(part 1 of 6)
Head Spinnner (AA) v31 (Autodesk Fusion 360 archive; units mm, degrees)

design "Head Spinnner (AA)" references "DC Motor Controller", "6V AA Battery Holder", "9V Battery & T Connector", "Plastic Latching Push Button", "LED + Cap", "Kwali on Pillar", "3 State Switch", "DC 6V 5RPM 2-Wire Motor"
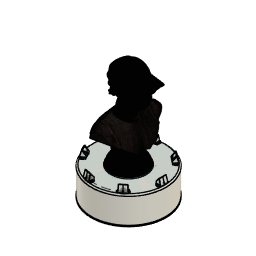
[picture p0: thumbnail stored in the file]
parameter "bustDiameter" = 83.82
parameter "wallThickness" = 3.175
parameter "clearance" = 0.254
parameter "buttonOffset" = 6.35
sketch "Profile" plane through (0, 0, 0) normal (0, 0, 1) x axis (1, 0, 0)
  circle C1 centre (0, 0) radius 41.91
  circle C2 centre (0, 0) radius 88.9
  point P1 (0, 0)
  point P2 (0, 0)
  coincident P1 P2
  concentric C1 C2
  dimension "d1" diameter C1 = 83.82 (= "bustDiameter")
  dimension "d2" diameter C2 = 177.8
extrude "Extrude1" new body sketch "Profile" along normal blind 63.5
shell "Shell1" innerThickness 3.175 (= "wallThickness")
fillet "Fillet1" radius 3.175
extrude "Extrude2" sketch "Profile" profile of C1 blind -132.08
sketch "PoR Clearance for Shell" plane through (0, 0, 63.5) normal (0, 0, 1) x axis (-1, 0, 0)
  circle C1 centre (0, 0) radius 41.91
  circle C2 centre (0, 0) radius 85.725
  circle C3 centre (0, 0) radius 42.164
  dimension "d136" = 0.254 (= "clearance")
extrude "Extrude4" cut sketch "PoR Clearance for Shell" profile of C1 C3 against normal blind 88.9
extrude "Extrude3" new body sketch "Profile" profile of C1 along normal blind 3.175
extrude "Extrude1" new body sketch "Profile" profile of C1 against normal blind 3.175
component_from_bodies "Body->Comp1"
component_from_bodies "Body->Comp2"
joint "Assemble1" alignAngle 0 alignOffsetX 0 alignOffsetY 0 alignOffsetZ 0
joint "Assemble2" alignAngle 0 alignOffsetX 0 alignOffsetY 0 alignOffsetZ 0
component_insert "Component Insert1"
component_insert "Component Insert2"
sketch "Gear OD" plane through (0, 0, 57.15) normal (0, 0, -1) x axis (0.9809, 0.1944, 0)
  circle C1 centre (0, 0) radius 41.91
  circle C2 centre (0, 0) radius 15.875
  concentric C1 C2
  dimension "d24" diameter C2 = 31.75
sketch "Sketch1" plane through (0, 0, 0) normal (0, 0, 1) x axis (1, 0, 0)
  circle C1 centre (0, 0) radius 12.6492
  circle C2 centre (0, 0) radius 3.175
extrude "Extrude1" new body sketch "Sketch1" along normal blind 25.4
sketch "Sketch2" plane through (0, 0, 0) normal (0, 0, 1) x axis (1, 0, 0)
  curve K1 (15.867, -0.5013) -> (13.5023, -1.2654)
  curve K2 (15.867, 0.5013) -> (13.5023, 1.2654)
  line L1 (13.5023, -1.2654) -> (12.584, -1.1803)
  line L2 (13.5023, 1.2654) -> (12.584, 1.1803)
  line L3 (12.584, 1.1803) -> (12.584, -1.1803)
  arc A1 centre (0, 0) radius 15.8749 clockwise from (15.867, 0.5013) to (15.867, -0.5013)
  dimension "d464" angle = 103.278
extrude "Extrude2" add sketch "Sketch2" along normal blind 25.4
fillet "Fillet1" radius 0.8382
circular_pattern "C-Pattern1" countU 20 TotalAngle 360
sketch "Sketch3" plane through (0, 0, 0) normal (0, 0, 1) x axis (1, 0, 0)
  circle C1 centre (0, 0) radius 14.4318
position "Position1"
combine "Combine1"
sketch "Holes for Shell Btm" plane through (0, 0, 0) normal (0, 0, -1) x axis (1, 0, 0)
  line L1 (0, -88.9) -> (0, -79.375)
  line L2 (0, -88.9) -> (0, 0)
  circle C1 centre (0, 0) radius 85.725
  circle C2 centre (0, 0) radius 88.9
  circle C3 centre (0, 0) radius 79.375
  circle C4 centre (0, -84.1375) radius 1.45
  circle C5 centre (65.7813, -52.4589) radius 1.45
  circle C6 centre (82.028, 18.7224) radius 1.45
  circle C7 centre (36.5059, 75.8053) radius 1.45
  circle C8 centre (-36.5059, 75.8053) radius 1.45
  circle C9 centre (-82.028, 18.7224) radius 1.45
  circle C10 centre (-65.7813, -52.4589) radius 1.45
  point P4 (0, -79.375)
  point P8 (0, -88.9)
  point P5 (0, -84.1375)
  point P6 (0, -84.1375)
  point P3 (0, 0)
  point P7 (0, 0)
  concentric C1 C3
  coincident C3 P4
  coincident C2 P8
  vertical L1
  midpoint L1 P5
  coincident P5 P6
  coincident P3 P7
  coincident C2 P8
  vertical L2
  dimension "d33" distance C2 C3 = 9.525 (= "( 3 / 8 ) * 1 in")
  dimension "d34" diameter C4 = 2.9
  dimension "d44" C-Pattern1-Angle = 360
extrude "Extrude1" add sketch "Holes for Shell Btm" profile of C1 C2 C3 C4 no distance stored
chamfer "Chamfer1" distance 6.35
sketch "Bottom Profile" plane through (0, 0, 0) normal (0, 0, -1) x axis (1, 0, 0)
  circle C1 centre (0, 0) radius 79.375
  circle C2 centre (0, 0) radius 88.9
  circle C3 centre (0, 0) radius 88.9
  concentric C1 C3
extrude "Extrude1" new body sketch "Bottom Profile" along normal blind 2.54
extrude "Extrude2" cut sketch "Holes for Shell Btm" profile of C4 C5 C6 C7 C8 C9 C10 distance 12.7
sketch "Bottom Holes" plane through (0, 0, -2.54) normal (0, 0, -1) x axis (1, 0, 0)
  circle C1 centre (36.5059, 75.8053) radius 1.45
  circle C2 centre (-65.7813, -52.4589) radius 1.45
  circle C3 centre (82.028, 18.7224) radius 1.45
  circle C4 centre (-36.5059, 75.8053) radius 1.45
  circle C5 centre (0, -84.1375) radius 1.45
  circle C6 centre (65.7813, -52.4589) radius 1.45
  circle C7 centre (-82.028, 18.7224) radius 1.45
  circle C8 centre (0, 0) radius 88.9
  circle C9 centre (0, -84.1375) radius 1.804
  circle C10 centre (65.7813, -52.4589) radius 1.804
  circle C11 centre (82.028, 18.7224) radius 1.804
  circle C12 centre (36.5059, 75.8053) radius 1.804
  circle C13 centre (-36.5059, 75.8053) radius 1.804
  circle C14 centre (-82.028, 18.7224) radius 1.804
  circle C15 centre (-65.7813, -52.4589) radius 1.804
  dimension "d526" = 0.354 (= "0.01 in + 0.1 mm")
  dimension "d52" C-Pattern1-Angle = 360
extrude "Extrude3" cut sketch "Bottom Holes" profile of C1 C2 C3 C4 C5 C6 C7 C9 C10 C11 C12 C13 C14 C15 against normal blind 38.1
chamfer "Chamfer1" distance 1.524
sketch "Sketch1" plane through (0, 0, 0) normal (0, 0, 1) x axis (1, 0, 0)
  circle C1 centre (0, 0) radius 19.865
  circle C2 centre (0, 0) radius 3.175
extrude "Extrude1" new body sketch "Sketch1" along normal blind 6.35
sketch "Sketch2" plane through (0, 0, 0) normal (0, 0, 1) x axis (1, 0, 0)
  curve K1 (23.0847, -0.5321) -> (20.2961, -1.3673)
  curve K2 (23.0847, 0.5321) -> (20.2961, 1.3673)
  line L1 (20.2961, -1.3673) -> (19.8101, -1.3352)
  line L2 (20.2961, 1.3673) -> (19.8101, 1.3352)
  line L3 (19.8101, 1.3352) -> (19.8101, -1.3352)
  arc A1 centre (0, 0) radius 23.0908 clockwise from (23.0847, 0.5321) to (23.0847, -0.5321)
extrude "Extrude2" add sketch "Sketch2" along normal blind 6.35
fillet "Fillet1" radius 0.8382
circular_pattern "C-Pattern1" countU 30 TotalAngle 360
sketch "Sketch3" plane through (0, 0, 0) normal (0, 0, 1) x axis (1, 0, 0)
  circle C1 centre (0, 0) radius 21.6477
sketch "Center Gear Pitch Diameter" plane through (0, 0, 0) normal (0, 0, -1) x axis (1, 0, 0)
  curve K1 (19.9155, 5.6104) -> (19.4097, 7.1671)
  curve K2 (21.3053, 8.9033) -> (19.4097, 7.1671)
  curve K3 (20.8725, 9.8754) -> (18.3138, 9.6284)
  curve K4 (18.3138, 9.6284) -> (17.4954, 11.046)
  curve K5 (18.9887, 13.1384) -> (17.4954, 11.046)
  curve K6 (18.3632, 13.9993) -> (15.9118, 13.2257)
  curve K7 (15.9118, 13.2257) -> (14.8165, 14.4421)
  curve K8 (15.8421, 16.7993) -> (14.8165, 14.4421)
  curve K9 (15.0513, 17.5113) -> (12.8143, 16.2449)
  curve K10 (12.8143, 16.2449) -> (11.49, 17.2071)
  curve K11 (12.0031, 19.7259) -> (11.49, 17.2071)
  curve K12 (11.0816, 20.258) -> (9.1567, 18.5542)
  curve K13 (9.1567, 18.5542) -> (7.6614, 19.22)
  curve K14 (7.6396, 21.7904) -> (7.6614, 19.22)
  curve K15 (6.6276, 22.1193) -> (5.099, 20.0525)
  curve K16 (5.099, 20.0525) -> (3.4979, 20.3928)
  curve K17 (2.9421, 22.9026) -> (3.4979, 20.3928)
  curve K18 (1.8839, 23.0139) -> (0.8184, 20.6745)
  curve K19 (0.8184, 20.6745) -> (-0.8184, 20.6745)
  curve K20 (-1.8839, 23.0139) -> (-0.8184, 20.6745)
  curve K21 (-2.9421, 22.9026) -> (-3.4979, 20.3928)
  curve K22 (-3.4979, 20.3928) -> (-5.099, 20.0525)
  curve K23 (-6.6276, 22.1193) -> (-5.099, 20.0525)
  curve K24 (-7.6396, 21.7904) -> (-7.6614, 19.22)
  curve K25 (-7.6614, 19.22) -> (-9.1567, 18.5542)
  curve K26 (-11.0816, 20.258) -> (-9.1567, 18.5542)
  curve K27 (-12.0031, 19.7259) -> (-11.49, 17.2071)
  curve K28 (-11.49, 17.2071) -> (-12.8143, 16.2449)
  curve K29 (-15.0513, 17.5113) -> (-12.8143, 16.2449)
  curve K30 (-15.8421, 16.7993) -> (-14.8165, 14.4421)
  curve K31 (-14.8165, 14.4421) -> (-15.9118, 13.2257)
  curve K32 (-18.3632, 13.9993) -> (-15.9118, 13.2257)
  curve K33 (-18.9887, 13.1384) -> (-17.4954, 11.046)
  curve K34 (-17.4954, 11.046) -> (-18.3138, 9.6284)
  curve K35 (-20.8725, 9.8754) -> (-18.3138, 9.6284)
  curve K36 (-21.3053, 8.9033) -> (-19.4097, 7.1671)
  curve K37 (-19.4097, 7.1671) -> (-19.9155, 5.6104)
  curve K38 (-22.4696, 5.32) -> (-19.9155, 5.6104)
  curve K39 (-22.6909, 4.2792) -> (-20.4757, 2.975)
  curve K40 (-20.4757, 2.975) -> (-20.6468, 1.3471)
  curve K41 (-23.0847, 0.5321) -> (-20.6468, 1.3471)
  curve K42 (-23.0847, -0.5321) -> (-20.6468, -1.3471)
  curve K43 (-20.6468, -1.3471) -> (-20.4757, -2.975)
  curve K44 (-22.6909, -4.2792) -> (-20.4757, -2.975)
  curve K45 (-22.4696, -5.32) -> (-19.9155, -5.6104)
  curve K46 (-19.9155, -5.6104) -> (-19.4097, -7.1671)
  curve K47 (-21.3053, -8.9033) -> (-19.4097, -7.1671)
  curve K48 (-20.8725, -9.8754) -> (-18.3138, -9.6284)
  curve K49 (-18.3138, -9.6284) -> (-17.4954, -11.046)
  curve K50 (-18.9887, -13.1384) -> (-17.4954, -11.046)
  curve K51 (-18.3632, -13.9993) -> (-15.9118, -13.2257)
  curve K52 (-15.9118, -13.2257) -> (-14.8165, -14.4421)
  curve K53 (-15.8421, -16.7993) -> (-14.8165, -14.4421)
  curve K54 (-15.0513, -17.5113) -> (-12.8143, -16.2449)
  curve K55 (-12.8143, -16.2449) -> (-11.49, -17.2071)
  curve K56 (-12.0031, -19.7259) -> (-11.49, -17.2071)
  curve K57 (-11.0816, -20.258) -> (-9.1567, -18.5542)
  curve K58 (-9.1567, -18.5542) -> (-7.6614, -19.22)
  curve K59 (-7.6396, -21.7904) -> (-7.6614, -19.22)
  curve K60 (-6.6276, -22.1193) -> (-5.099, -20.0525)
  curve K61 (-5.099, -20.0525) -> (-3.4979, -20.3928)
  curve K62 (-2.9421, -22.9026) -> (-3.4979, -20.3928)
  curve K63 (-1.8839, -23.0139) -> (-0.8184, -20.6745)
  curve K64 (-0.8184, -20.6745) -> (0.8184, -20.6745)
  curve K65 (1.8839, -23.0139) -> (0.8184, -20.6745)
  curve K66 (2.9421, -22.9026) -> (3.4979, -20.3928)
  curve K67 (3.4979, -20.3928) -> (5.099, -20.0525)
  curve K68 (6.6276, -22.1193) -> (5.099, -20.0525)
  curve K69 (7.6396, -21.7904) -> (7.6614, -19.22)
  curve K70 (7.6614, -19.22) -> (9.1567, -18.5542)
  curve K71 (11.0816, -20.258) -> (9.1567, -18.5542)
  curve K72 (12.0031, -19.7259) -> (11.49, -17.2071)
  curve K73 (11.49, -17.2071) -> (12.8143, -16.2449)
  curve K74 (15.0513, -17.5113) -> (12.8143, -16.2449)
  curve K75 (15.8421, -16.7993) -> (14.8165, -14.4421)
  curve K76 (14.8165, -14.4421) -> (15.9118, -13.2257)
  curve K77 (18.3632, -13.9993) -> (15.9118, -13.2257)
  curve K78 (18.9887, -13.1384) -> (17.4954, -11.046)
  curve K79 (17.4954, -11.046) -> (18.3138, -9.6284)
  curve K80 (20.8725, -9.8754) -> (18.3138, -9.6284)
  curve K81 (21.3053, -8.9033) -> (19.4097, -7.1671)
  curve K82 (19.4097, -7.1671) -> (19.9155, -5.6104)
  curve K83 (22.4696, -5.32) -> (19.9155, -5.6104)
  curve K84 (22.6909, -4.2792) -> (20.4757, -2.975)
  curve K85 (20.4757, -2.975) -> (20.6468, -1.3471)
  curve K86 (23.0847, -0.5321) -> (20.6468, -1.3471)
  curve K87 (23.0847, 0.5321) -> (20.6468, 1.3471)
  curve K88 (20.6468, 1.3471) -> (20.4757, 2.975)
  curve K89 (22.6909, 4.2792) -> (20.4757, 2.975)
  curve K90 (22.4696, 5.32) -> (19.9155, 5.6104)
  arc A1 centre (0, 0) radius 23.0908 clockwise from (20.8725, 9.8754) to (21.3053, 8.9033)
  arc A2 centre (0, 0) radius 23.0908 clockwise from (18.3632, 13.9993) to (18.9887, 13.1384)
  arc A3 centre (0, 0) radius 23.0908 clockwise from (15.0513, 17.5113) to (15.8421, 16.7993)
  arc A4 centre (0, 0) radius 23.0908 clockwise from (11.0816, 20.258) to (12.0031, 19.7259)
  arc A5 centre (0, 0) radius 23.0908 clockwise from (6.6276, 22.1193) to (7.6396, 21.7904)
  arc A6 centre (0, 0) radius 23.0908 clockwise from (1.8839, 23.0139) to (2.9421, 22.9026)
  arc A7 centre (0, 0) radius 23.0908 clockwise from (-2.9421, 22.9026) to (-1.8839, 23.0139)
  arc A8 centre (0, 0) radius 23.0908 clockwise from (-7.6396, 21.7904) to (-6.6276, 22.1193)
  arc A9 centre (0, 0) radius 23.0908 clockwise from (-12.0031, 19.7259) to (-11.0816, 20.258)
  arc A10 centre (0, 0) radius 23.0908 clockwise from (-15.8421, 16.7993) to (-15.0513, 17.5113)
  arc A11 centre (0, 0) radius 23.0908 clockwise from (-18.9887, 13.1384) to (-18.3632, 13.9993)
  arc A12 centre (0, 0) radius 23.0908 clockwise from (-21.3053, 8.9033) to (-20.8725, 9.8754)
  arc A13 centre (0, 0) radius 23.0908 clockwise from (-22.6909, 4.2792) to (-22.4696, 5.32)
  arc A14 centre (0, 0) radius 23.0908 clockwise from (-23.0847, -0.5321) to (-23.0847, 0.5321)
  arc A15 centre (0, 0) radius 23.0908 clockwise from (-22.4696, -5.32) to (-22.6909, -4.2792)
  arc A16 centre (0, 0) radius 23.0908 clockwise from (-20.8725, -9.8754) to (-21.3053, -8.9033)
  arc A17 centre (0, 0) radius 23.0908 clockwise from (-18.3632, -13.9993) to (-18.9887, -13.1384)
  arc A18 centre (0, 0) radius 23.0908 clockwise from (-15.0513, -17.5113) to (-15.8421, -16.7993)
  arc A19 centre (0, 0) radius 23.0908 clockwise from (-11.0816, -20.258) to (-12.0031, -19.7259)
  arc A20 centre (0, 0) radius 23.0908 clockwise from (-6.6276, -22.1193) to (-7.6396, -21.7904)
  arc A21 centre (0, 0) radius 23.0908 clockwise from (-1.8839, -23.0139) to (-2.9421, -22.9026)
  arc A22 centre (0, 0) radius 23.0908 clockwise from (2.9421, -22.9026) to (1.8839, -23.0139)
  arc A23 centre (0, 0) radius 23.0908 clockwise from (7.6396, -21.7904) to (6.6276, -22.1193)
  arc A24 centre (0, 0) radius 23.0908 clockwise from (12.0031, -19.7259) to (11.0816, -20.258)
  arc A25 centre (0, 0) radius 23.0908 clockwise from (15.8421, -16.7993) to (15.0513, -17.5113)
  arc A26 centre (0, 0) radius 23.0908 clockwise from (18.9887, -13.1384) to (18.3632, -13.9993)
  arc A27 centre (0, 0) radius 23.0908 clockwise from (21.3053, -8.9033) to (20.8725, -9.8754)
  arc A28 centre (0, 0) radius 23.0908 clockwise from (22.6909, -4.2792) to (22.4696, -5.32)
  arc A29 centre (0, 0) radius 23.0908 clockwise from (23.0847, 0.5321) to (23.0847, -0.5321)
  arc A30 centre (0, 0) radius 23.0908 clockwise from (22.4696, 5.32) to (22.6909, 4.2792)
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extrude "Extrude5" add sketch "Center Gear Pitch Diameter" against normal blind 6.35
sketch "Motor Shaft Profile for Gear" plane through (0, 0, 0) normal (0, 0, -1) x axis (1, 0, 0)
  curve K1 (19.9155, 5.6104) -> (19.4097, 7.1671)
  curve K2 (21.3053, 8.9033) -> (19.4097, 7.1671)
  curve K3 (20.8725, 9.8754) -> (18.3138, 9.6284)
  curve K4 (18.3138, 9.6284) -> (17.4954, 11.046)
  curve K5 (18.9887, 13.1384) -> (17.4954, 11.046)
  curve K6 (18.3632, 13.9993) -> (15.9118, 13.2257)
  curve K7 (15.9118, 13.2257) -> (14.8165, 14.4421)
  curve K8 (15.8421, 16.7993) -> (14.8165, 14.4421)
  curve K9 (15.0513, 17.5113) -> (12.8143, 16.2449)
  curve K10 (12.8143, 16.2449) -> (11.49, 17.2071)
  curve K11 (12.0031, 19.7259) -> (11.49, 17.2071)
  curve K12 (11.0816, 20.258) -> (9.1567, 18.5542)
  curve K13 (9.1567, 18.5542) -> (7.6614, 19.22)
  curve K14 (7.6396, 21.7904) -> (7.6614, 19.22)
  curve K15 (6.6276, 22.1193) -> (5.099, 20.0525)
  curve K16 (5.099, 20.0525) -> (3.4979, 20.3928)
  curve K17 (2.9421, 22.9026) -> (3.4979, 20.3928)
  curve K18 (1.8839, 23.0139) -> (0.8184, 20.6745)
  curve K19 (0.8184, 20.6745) -> (-0.8184, 20.6745)
  curve K20 (-1.8839, 23.0139) -> (-0.8184, 20.6745)
  curve K21 (-2.9421, 22.9026) -> (-3.4979, 20.3928)
  curve K22 (-3.4979, 20.3928) -> (-5.099, 20.0525)
  curve K23 (-6.6276, 22.1193) -> (-5.099, 20.0525)
  curve K24 (-7.6396, 21.7904) -> (-7.6614, 19.22)
  curve K25 (-7.6614, 19.22) -> (-9.1567, 18.5542)
  curve K26 (-11.0816, 20.258) -> (-9.1567, 18.5542)
  curve K27 (-12.0031, 19.7259) -> (-11.49, 17.2071)
  curve K28 (-11.49, 17.2071) -> (-12.8143, 16.2449)
  curve K29 (-15.0513, 17.5113) -> (-12.8143, 16.2449)
  curve K30 (-15.8421, 16.7993) -> (-14.8165, 14.4421)
  curve K31 (-14.8165, 14.4421) -> (-15.9118, 13.2257)
  curve K32 (-18.3632, 13.9993) -> (-15.9118, 13.2257)
  curve K33 (-18.9887, 13.1384) -> (-17.4954, 11.046)
  curve K34 (-17.4954, 11.046) -> (-18.3138, 9.6284)
  curve K35 (-20.8725, 9.8754) -> (-18.3138, 9.6284)
  curve K36 (-21.3053, 8.9033) -> (-19.4097, 7.1671)
  curve K37 (-19.4097, 7.1671) -> (-19.9155, 5.6104)
  curve K38 (-22.4696, 5.32) -> (-19.9155, 5.6104)
  curve K39 (-22.6909, 4.2792) -> (-20.4757, 2.975)
  curve K40 (-20.4757, 2.975) -> (-20.6468, 1.3471)
  curve K41 (-23.0847, 0.5321) -> (-20.6468, 1.3471)
  curve K42 (-23.0847, -0.5321) -> (-20.6468, -1.3471)
  curve K43 (-20.6468, -1.3471) -> (-20.4757, -2.975)
  curve K44 (-22.6909, -4.2792) -> (-20.4757, -2.975)
  curve K45 (-22.4696, -5.32) -> (-19.9155, -5.6104)
  curve K46 (-19.9155, -5.6104) -> (-19.4097, -7.1671)
  curve K47 (-21.3053, -8.9033) -> (-19.4097, -7.1671)
  curve K48 (-20.8725, -9.8754) -> (-18.3138, -9.6284)
  curve K49 (-18.3138, -9.6284) -> (-17.4954, -11.046)
  curve K50 (-18.9887, -13.1384) -> (-17.4954, -11.046)
  curve K51 (-18.3632, -13.9993) -> (-15.9118, -13.2257)
  curve K52 (-15.9118, -13.2257) -> (-14.8165, -14.4421)
  curve K53 (-15.8421, -16.7993) -> (-14.8165, -14.4421)
  curve K54 (-15.0513, -17.5113) -> (-12.8143, -16.2449)
  curve K55 (-12.8143, -16.2449) -> (-11.49, -17.2071)
  curve K56 (-12.0031, -19.7259) -> (-11.49, -17.2071)
  curve K57 (-11.0816, -20.258) -> (-9.1567, -18.5542)
  curve K58 (-9.1567, -18.5542) -> (-7.6614, -19.22)
  curve K59 (-7.6396, -21.7904) -> (-7.6614, -19.22)
  curve K60 (-6.6276, -22.1193) -> (-5.099, -20.0525)
  curve K61 (-5.099, -20.0525) -> (-3.4979, -20.3928)
  curve K62 (-2.9421, -22.9026) -> (-3.4979, -20.3928)
  curve K63 (-1.8839, -23.0139) -> (-0.8184, -20.6745)
  curve K64 (-0.8184, -20.6745) -> (0.8184, -20.6745)
  curve K65 (1.8839, -23.0139) -> (0.8184, -20.6745)
  curve K66 (2.9421, -22.9026) -> (3.4979, -20.3928)
  curve K67 (3.4979, -20.3928) -> (5.099, -20.0525)
  curve K68 (6.6276, -22.1193) -> (5.099, -20.0525)
  curve K69 (7.6396, -21.7904) -> (7.6614, -19.22)
  curve K70 (7.6614, -19.22) -> (9.1567, -18.5542)
  curve K71 (11.0816, -20.258) -> (9.1567, -18.5542)
  curve K72 (12.0031, -19.7259) -> (11.49, -17.2071)
  curve K73 (11.49, -17.2071) -> (12.8143, -16.2449)
  curve K74 (15.0513, -17.5113) -> (12.8143, -16.2449)
  curve K75 (15.8421, -16.7993) -> (14.8165, -14.4421)
  curve K76 (14.8165, -14.4421) -> (15.9118, -13.2257)
  curve K77 (18.3632, -13.9993) -> (15.9118, -13.2257)
  curve K78 (18.9887, -13.1384) -> (17.4954, -11.046)
  curve K79 (17.4954, -11.046) -> (18.3138, -9.6284)
  curve K80 (20.8725, -9.8754) -> (18.3138, -9.6284)
  curve K81 (21.3053, -8.9033) -> (19.4097, -7.1671)
  curve K82 (19.4097, -7.1671) -> (19.9155, -5.6104)
  curve K83 (22.4696, -5.32) -> (19.9155, -5.6104)
  curve K84 (22.6909, -4.2792) -> (20.4757, -2.975)
  curve K85 (20.4757, -2.975) -> (20.6468, -1.3471)
  curve K86 (23.0847, -0.5321) -> (20.6468, -1.3471)
  curve K87 (23.0847, 0.5321) -> (20.6468, 1.3471)
  curve K88 (20.6468, 1.3471) -> (20.4757, 2.975)
  curve K89 (22.6909, 4.2792) -> (20.4757, 2.975)
  curve K90 (22.4696, 5.32) -> (19.9155, 5.6104)
  line L1 (-2.0225, -1.4964) -> (-2.0225, 1.4964)
  line L2 (2.0225, -1.4964) -> (2.0225, 1.4964)
  line L3 (2.0225, 0) -> (-2.0225, 0)
  arc A1 centre (0, 0) radius 23.0908 clockwise from (20.8725, 9.8754) to (21.3053, 8.9033)
  arc A2 centre (0, 0) radius 23.0908 clockwise from (18.3632, 13.9993) to (18.9887, 13.1384)
  arc A3 centre (0, 0) radius 23.0908 clockwise from (15.0513, 17.5113) to (15.8421, 16.7993)
  arc A4 centre (0, 0) radius 23.0908 clockwise from (11.0816, 20.258) to (12.0031, 19.7259)
  arc A5 centre (0, 0) radius 23.0908 clockwise from (6.6276, 22.1193) to (7.6396, 21.7904)
  arc A6 centre (0, 0) radius 23.0908 clockwise from (1.8839, 23.0139) to (2.9421, 22.9026)
  arc A7 centre (0, 0) radius 23.0908 clockwise from (-2.9421, 22.9026) to (-1.8839, 23.0139)
  arc A8 centre (0, 0) radius 23.0908 clockwise from (-7.6396, 21.7904) to (-6.6276, 22.1193)
  arc A9 centre (0, 0) radius 23.0908 clockwise from (-12.0031, 19.7259) to (-11.0816, 20.258)
  arc A10 centre (0, 0) radius 23.0908 clockwise from (-15.8421, 16.7993) to (-15.0513, 17.5113)
  arc A11 centre (0, 0) radius 23.0908 clockwise from (-18.9887, 13.1384) to (-18.3632, 13.9993)
  arc A12 centre (0, 0) radius 23.0908 clockwise from (-21.3053, 8.9033) to (-20.8725, 9.8754)
  arc A13 centre (0, 0) radius 23.0908 clockwise from (-22.6909, 4.2792) to (-22.4696, 5.32)
  arc A14 centre (0, 0) radius 23.0908 clockwise from (-23.0847, -0.5321) to (-23.0847, 0.5321)
  arc A15 centre (0, 0) radius 23.0908 clockwise from (-22.4696, -5.32) to (-22.6909, -4.2792)
  arc A16 centre (0, 0) radius 23.0908 clockwise from (-20.8725, -9.8754) to (-21.3053, -8.9033)
  arc A17 centre (0, 0) radius 23.0908 clockwise from (-18.3632, -13.9993) to (-18.9887, -13.1384)
  arc A18 centre (0, 0) radius 23.0908 clockwise from (-15.0513, -17.5113) to (-15.8421, -16.7993)
  arc A19 centre (0, 0) radius 23.0908 clockwise from (-11.0816, -20.258) to (-12.0031, -19.7259)
  arc A20 centre (0, 0) radius 23.0908 clockwise from (-6.6276, -22.1193) to (-7.6396, -21.7904)
  arc A21 centre (0, 0) radius 23.0908 clockwise from (-1.8839, -23.0139) to (-2.9421, -22.9026)
  arc A22 centre (0, 0) radius 23.0908 clockwise from (2.9421, -22.9026) to (1.8839, -23.0139)
  arc A23 centre (0, 0) radius 23.0908 clockwise from (7.6396, -21.7904) to (6.6276, -22.1193)
  arc A24 centre (0, 0) radius 23.0908 clockwise from (12.0031, -19.7259) to (11.0816, -20.258)
  arc A25 centre (0, 0) radius 23.0908 clockwise from (15.8421, -16.7993) to (15.0513, -17.5113)
  arc A26 centre (0, 0) radius 23.0908 clockwise from (18.9887, -13.1384) to (18.3632, -13.9993)
  arc A27 centre (0, 0) radius 23.0908 clockwise from (21.3053, -8.9033) to (20.8725, -9.8754)
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  point P1 (0, 0)
  point P123 (0, 0)
  point P129 (2.0225, 0)
  point P128 (-2.0225, 0)
  point P130 (0, 0)
  coincident P1 P123
  vertical L1
  parallel L1 L2
  midpoint L2 P129
  perpendicular L2 L3
  midpoint L1 P128
  midpoint L3 P130
  coincident P1 P130
  dimension "d65" diameter = 5.0318 (= "5 mm + 0.00125 in")
  dimension "d66" distance P128 P129 = 4.045 (= "0.158 in + 0.00125 in")
  dimension "d68" distance = 2.54
extrude "Extrude4" add sketch "Motor Shaft Profile for Gear" along normal blind 5.08
joint "Assemble3" alignAngle 90 alignOffsetX 0 alignOffsetY 0 alignOffsetZ 0
sketch "Gear Placement" plane through (0, 0, 0) normal (0, 0, -1) x axis (1, 0, 0)
  line L1 (1.27, 0) -> (0, 0)
  line L2 (36.0794, 0) -> (1.27, 0)
  circle C1 centre (36.5059, 75.8053) radius 1.45
  circle C2 centre (-65.7813, -52.4589) radius 1.45
  circle C3 centre (82.028, 18.7224) radius 1.45
  circle C4 centre (-36.5059, 75.8053) radius 1.45
  circle C5 centre (0, -84.1375) radius 1.45
  circle C6 centre (65.7813, -52.4589) radius 1.45
  circle C7 centre (-82.028, 18.7224) radius 1.45
  circle C8 centre (0, 0) radius 79.375
  circle C9 centre (0, 0) radius 88.9
  circle C10 centre (36.0794, 0) radius 21.6477
  circle C11 centre (0, 0) radius 14.4318
  point P11 (0, 0)
  point P12 (0, 0)
  point P10 (36.0794, 0)
  point P14 (36.0794, 0)
  tangent C10 C11
  coincident P11 P12
  horizontal L1
  coincident P10 P14
  horizontal L2
  dimension "d77" diameter C10 = 43.2953
position "Position2"
joint "Assemble7" alignAngle 0 alignOffsetX 0 alignOffsetY 0 alignOffsetZ 0
position "Position3"
sketch "Sketch4" plane through (0, 0, 6.35) normal (0, 0, 1) x axis (-1, 0, 0)
  curve K1 (-23.0847, 0.5321) -> (-20.6468, 1.3471)
  curve K2 (-20.6468, -1.3471) -> (-23.0847, -0.5321)
  curve K3 (-20.6468, -1.3471) -> (-20.4757, -2.975)
  curve K4 (-22.6909, -4.2792) -> (-20.4757, -2.975)
  curve K5 (-19.9155, -5.6104) -> (-22.4696, -5.32)
  curve K6 (-19.9155, -5.6104) -> (-19.4097, -7.1671)
  curve K7 (-21.3053, -8.9033) -> (-19.4097, -7.1671)
  curve K8 (-18.3138, -9.6284) -> (-20.8725, -9.8754)
  curve K9 (-18.3138, -9.6284) -> (-17.4954, -11.046)
  curve K10 (-18.9887, -13.1384) -> (-17.4954, -11.046)
  curve K11 (-15.9118, -13.2257) -> (-18.3632, -13.9993)
  curve K12 (-15.9118, -13.2257) -> (-14.8165, -14.4421)
  curve K13 (-15.8421, -16.7993) -> (-14.8165, -14.4421)
  curve K14 (-12.8143, -16.2449) -> (-15.0513, -17.5113)
  curve K15 (-12.8143, -16.2449) -> (-11.49, -17.2071)
  curve K16 (-12.0031, -19.7259) -> (-11.49, -17.2071)
  curve K17 (-9.1567, -18.5542) -> (-11.0816, -20.258)
  curve K18 (-9.1567, -18.5542) -> (-7.6614, -19.22)
  curve K19 (-7.6396, -21.7904) -> (-7.6614, -19.22)
  curve K20 (-5.099, -20.0525) -> (-6.6276, -22.1193)
  curve K21 (-5.099, -20.0525) -> (-3.4979, -20.3928)
  curve K22 (-2.9421, -22.9026) -> (-3.4979, -20.3928)
  curve K23 (-0.8184, -20.6745) -> (-1.8839, -23.0139)
  curve K24 (-0.8184, -20.6745) -> (0.8184, -20.6745)
  curve K25 (1.8839, -23.0139) -> (0.8184, -20.6745)
  curve K26 (3.4979, -20.3928) -> (2.9421, -22.9026)
  curve K27 (3.4979, -20.3928) -> (5.099, -20.0525)
  curve K28 (6.6276, -22.1193) -> (5.099, -20.0525)
  curve K29 (7.6614, -19.22) -> (7.6396, -21.7904)
  curve K30 (7.6614, -19.22) -> (9.1567, -18.5542)
  curve K31 (11.0816, -20.258) -> (9.1567, -18.5542)
  curve K32 (11.49, -17.2071) -> (12.0031, -19.7259)
  curve K33 (11.49, -17.2071) -> (12.8143, -16.2449)
  curve K34 (15.0513, -17.5113) -> (12.8143, -16.2449)
  curve K35 (14.8165, -14.4421) -> (15.8421, -16.7993)
  curve K36 (14.8165, -14.4421) -> (15.9118, -13.2257)
  curve K37 (18.3632, -13.9993) -> (15.9118, -13.2257)
  curve K38 (17.4954, -11.046) -> (18.9887, -13.1384)
  curve K39 (17.4954, -11.046) -> (18.3138, -9.6284)
  curve K40 (20.8725, -9.8754) -> (18.3138, -9.6284)
  curve K41 (19.4097, -7.1671) -> (21.3053, -8.9033)
  curve K42 (19.4097, -7.1671) -> (19.9155, -5.6104)
  curve K43 (22.4696, -5.32) -> (19.9155, -5.6104)
  curve K44 (20.4757, -2.975) -> (22.6909, -4.2792)
  curve K45 (20.4757, -2.975) -> (20.6468, -1.3471)
  curve K46 (23.0847, -0.5321) -> (20.6468, -1.3471)
  curve K47 (20.6468, 1.3471) -> (23.0847, 0.5321)
  curve K48 (20.6468, 1.3471) -> (20.4757, 2.975)
  curve K49 (22.6909, 4.2792) -> (20.4757, 2.975)
  curve K50 (19.9155, 5.6104) -> (22.4696, 5.32)
  curve K51 (19.9155, 5.6104) -> (19.4097, 7.1671)
  curve K52 (21.3053, 8.9033) -> (19.4097, 7.1671)
  curve K53 (18.3138, 9.6284) -> (20.8725, 9.8754)
  curve K54 (18.3138, 9.6284) -> (17.4954, 11.046)
  curve K55 (18.9887, 13.1384) -> (17.4954, 11.046)
  curve K56 (15.9118, 13.2257) -> (18.3632, 13.9993)
  curve K57 (15.9118, 13.2257) -> (14.8165, 14.4421)
  curve K58 (15.8421, 16.7993) -> (14.8165, 14.4421)
  curve K59 (12.8143, 16.2449) -> (15.0513, 17.5113)
  curve K60 (12.8143, 16.2449) -> (11.49, 17.2071)
  curve K61 (12.0031, 19.7259) -> (11.49, 17.2071)
  curve K62 (9.1567, 18.5542) -> (11.0816, 20.258)
  curve K63 (9.1567, 18.5542) -> (7.6614, 19.22)
  curve K64 (7.6396, 21.7904) -> (7.6614, 19.22)
  curve K65 (5.099, 20.0525) -> (6.6276, 22.1193)
  curve K66 (5.099, 20.0525) -> (3.4979, 20.3928)
  curve K67 (2.9421, 22.9026) -> (3.4979, 20.3928)
  curve K68 (0.8184, 20.6745) -> (1.8839, 23.0139)
  curve K69 (0.8184, 20.6745) -> (-0.8184, 20.6745)
  curve K70 (-1.8839, 23.0139) -> (-0.8184, 20.6745)
  curve K71 (-3.4979, 20.3928) -> (-2.9421, 22.9026)
  curve K72 (-3.4979, 20.3928) -> (-5.099, 20.0525)
  curve K73 (-6.6276, 22.1193) -> (-5.099, 20.0525)
  curve K74 (-7.6614, 19.22) -> (-7.6396, 21.7904)
  curve K75 (-7.6614, 19.22) -> (-9.1567, 18.5542)
  curve K76 (-11.0816, 20.258) -> (-9.1567, 18.5542)
  curve K77 (-11.49, 17.2071) -> (-12.0031, 19.7259)
  curve K78 (-11.49, 17.2071) -> (-12.8143, 16.2449)
  curve K79 (-15.0513, 17.5113) -> (-12.8143, 16.2449)
  curve K80 (-14.8165, 14.4421) -> (-15.8421, 16.7993)
  curve K81 (-14.8165, 14.4421) -> (-15.9118, 13.2257)
  curve K82 (-18.3632, 13.9993) -> (-15.9118, 13.2257)
  curve K83 (-17.4954, 11.046) -> (-18.9887, 13.1384)
  curve K84 (-17.4954, 11.046) -> (-18.3138, 9.6284)
  curve K85 (-20.8725, 9.8754) -> (-18.3138, 9.6284)
  curve K86 (-19.4097, 7.1671) -> (-21.3053, 8.9033)
  curve K87 (-19.4097, 7.1671) -> (-19.9155, 5.6104)
  curve K88 (-22.4696, 5.32) -> (-19.9155, 5.6104)
  curve K89 (-20.4757, 2.975) -> (-22.6909, 4.2792)
  curve K90 (-20.4757, 2.975) -> (-20.6468, 1.3471)
  arc A1 centre (0, 0) radius 23.0908 clockwise from (-23.0847, -0.5321) to (-23.0847, 0.5321)
  arc A2 centre (0, 0) radius 23.0908 clockwise from (-22.4696, -5.32) to (-22.6909, -4.2792)
  arc A3 centre (0, 0) radius 23.0908 clockwise from (-20.8725, -9.8754) to (-21.3053, -8.9033)
  arc A4 centre (0, 0) radius 23.0908 clockwise from (-18.3632, -13.9993) to (-18.9887, -13.1384)
  arc A5 centre (0, 0) radius 23.0908 clockwise from (-15.0513, -17.5113) to (-15.8421, -16.7993)
  arc A6 centre (0, 0) radius 23.0908 clockwise from (-11.0816, -20.258) to (-12.0031, -19.7259)
  arc A7 centre (0, 0) radius 23.0908 clockwise from (-6.6276, -22.1193) to (-7.6396, -21.7904)
  arc A8 centre (0, 0) radius 23.0908 clockwise from (-1.8839, -23.0139) to (-2.9421, -22.9026)
  arc A9 centre (0, 0) radius 23.0908 clockwise from (2.9421, -22.9026) to (1.8839, -23.0139)
  arc A10 centre (0, 0) radius 23.0908 clockwise from (7.6396, -21.7904) to (6.6276, -22.1193)
  arc A11 centre (0, 0) radius 23.0908 clockwise from (12.0031, -19.7259) to (11.0816, -20.258)
  arc A12 centre (0, 0) radius 23.0908 clockwise from (15.8421, -16.7993) to (15.0513, -17.5113)
  arc A13 centre (0, 0) radius 23.0908 clockwise from (18.9887, -13.1384) to (18.3632, -13.9993)
  arc A14 centre (0, 0) radius 23.0908 clockwise from (21.3053, -8.9033) to (20.8725, -9.8754)
  arc A15 centre (0, 0) radius 23.0908 clockwise from (22.6909, -4.2792) to (22.4696, -5.32)
  arc A16 centre (0, 0) radius 23.0908 clockwise from (23.0847, 0.5321) to (23.0847, -0.5321)
  arc A17 centre (0, 0) radius 23.0908 clockwise from (22.4696, 5.32) to (22.6909, 4.2792)
  arc A18 centre (0, 0) radius 23.0908 clockwise from (20.8725, 9.8754) to (21.3053, 8.9033)
  arc A19 centre (0, 0) radius 23.0908 clockwise from (18.3632, 13.9993) to (18.9887, 13.1384)
  arc A20 centre (0, 0) radius 23.0908 clockwise from (15.0513, 17.5113) to (15.8421, 16.7993)
  arc A21 centre (0, 0) radius 23.0908 clockwise from (11.0816, 20.258) to (12.0031, 19.7259)
  arc A22 centre (0, 0) radius 23.0908 clockwise from (6.6276, 22.1193) to (7.6396, 21.7904)
  arc A23 centre (0, 0) radius 23.0908 clockwise from (1.8839, 23.0139) to (2.9421, 22.9026)
  arc A24 centre (0, 0) radius 23.0908 clockwise from (-2.9421, 22.9026) to (-1.8839, 23.0139)
  arc A25 centre (0, 0) radius 23.0908 clockwise from (-7.6396, 21.7904) to (-6.6276, 22.1193)
  arc A26 centre (0, 0) radius 23.0908 clockwise from (-12.0031, 19.7259) to (-11.0816, 20.258)
  arc A27 centre (0, 0) radius 23.0908 clockwise from (-15.8421, 16.7993) to (-15.0513, 17.5113)
  arc A28 centre (0, 0) radius 23.0908 clockwise from (-18.9887, 13.1384) to (-18.3632, 13.9993)
  arc A29 centre (0, 0) radius 23.0908 clockwise from (-21.3053, 8.9033) to (-20.8725, 9.8754)
  arc A30 centre (0, 0) radius 23.0908 clockwise from (-22.6909, 4.2792) to (-22.4696, 5.32)
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  point P1 (0, 0)
  point P123 (0, 0)
  coincident P1 P123
  dimension "d440" diameter = 3.5
extrude "Extrude6" cut sketch "Sketch4" against normal blind 35.56
sketch "Motor Housing Profile (H)" plane through (0, 0, 0) normal (0, 0, 1) x axis (-1, 0, 0)
  line L1 (-40.8927, 19.5) -> (-40.8927, 15.6709)
  line L2 (-49.0461, 15.6709) -> (-49.0461, 19.5)
  line L3 (-49.0461, -19.5) -> (-49.0461, -15.6709)
  line L4 (-40.8927, -15.6709) -> (-40.8927, -19.5)
  line L5 (-40.7657, -15.7688) -> (-40.7657, -19.5)
  line L6 (-40.7657, 19.5) -> (-40.7657, 15.7688)
  line L7 (-49.1731, 15.7688) -> (-49.1731, 19.5)
  line L8 (-49.1731, -19.5) -> (-49.1731, -15.7688)
  line L9 (-37.8447, -17.8728) -> (-37.8447, -19.5)
  line L10 (-37.8447, 19.5) -> (-37.8447, 17.8728)
  line L11 (-52.0941, 17.8728) -> (-52.0941, 19.5)
  line L12 (-52.0941, -19.5) -> (-52.0941, -17.8728)
  circle C1 centre (0, -84.1375) radius 1.804
  circle C2 centre (-36.5059, 75.8053) radius 1.804
  circle C3 centre (36.5059, 75.8053) radius 1.804
  circle C4 centre (-65.7813, -52.4589) radius 1.804
  circle C5 centre (65.7813, -52.4589) radius 1.804
  circle C6 centre (-82.028, 18.7224) radius 1.804
  circle C7 centre (82.028, 18.7224) radius 1.804
  circle C8 centre (0, 0) radius 88.9
  circle C9 centre (-44.9694, 19.5) radius 1.625
  circle C10 centre (-44.9694, -19.5) radius 1.625
  arc A1 centre (-44.9694, 0) radius 16.1925 clockwise from (-40.8927, 15.6709) to (-40.8927, -15.6709)
  arc A2 centre (-44.9694, 19.5) radius 4.0767 clockwise from (-49.0461, 19.5) to (-40.8927, 19.5)
  arc A3 centre (-44.9694, 0) radius 16.1925 clockwise from (-49.0461, -15.6709) to (-49.0461, 15.6709)
  arc A4 centre (-44.9694, -19.5) radius 4.0767 clockwise from (-40.8927, -19.5) to (-49.0461, -19.5)
  arc A5 centre (-44.9694, -19.5) radius 4.2037 clockwise from (-40.7657, -19.5) to (-49.1731, -19.5)
  arc A6 centre (-44.9694, 0) radius 16.3195 clockwise from (-40.7657, 15.7688) to (-40.7657, -15.7688)
  arc A7 centre (-44.9694, 19.5) radius 4.2037 clockwise from (-49.1731, 19.5) to (-40.7657, 19.5)
  arc A8 centre (-44.9694, 0) radius 16.3195 clockwise from (-49.1731, -15.7688) to (-49.1731, 15.7688)
  arc A9 centre (-44.9694, -19.5) radius 7.1247 clockwise from (-37.8447, -19.5) to (-52.0941, -19.5)
  arc A10 centre (-44.9694, 0) radius 19.2405 clockwise from (-37.8447, 17.8728) to (-37.8447, -17.8728)
  arc A11 centre (-44.9694, 19.5) radius 7.1247 clockwise from (-52.0941, 19.5) to (-37.8447, 19.5)
  arc A12 centre (-44.9694, 0) radius 19.2405 clockwise from (-52.0941, -17.8728) to (-52.0941, 17.8728)
  circle C11 centre (-44.9694, 0) radius 16.3195
  circle C12 centre (-36.0794, 0) radius 1.5
  concentric A1 C11
  tangent A6 C11
  dimension "d107" = 0.127 (= "clearance / 2")
  dimension "d108" = 3.048 (= "0.1 in + clearance * 2")
extrude "Extrude7" add sketch "Motor Housing Profile (H)" profile of L8 A8 A7 L6 L5 L7 A6 A5 L12 A12 A11 L10 L9 L11 A10 A9 C11 along normal blind 25.0063
sketch "Motor Housing Profile (S)" plane through (0, 0, 25.0063) normal (0, 0, 1) x axis (-1, 0, 0)
  line L1 (-52.0941, -19.5) -> (-52.0941, -17.8728)
  line L2 (-37.8447, -17.8728) -> (-37.8447, -19.5)
  line L3 (-37.8447, 19.5) -> (-37.8447, 17.8728)
  line L4 (-52.0941, 17.8728) -> (-52.0941, 19.5)
  line L5 (-40.7657, 19.5) -> (-40.7657, 15.7688)
  line L6 (-49.1731, 15.7688) -> (-49.1731, 19.5)
  line L7 (-40.7657, -15.7688) -> (-40.7657, -19.5)
  line L8 (-49.1731, -19.5) -> (-49.1731, -15.7688)
  line L9 (-63.3416, 5.715) -> (-60.2555, 5.715)
  line L10 (-63.3416, -5.715) -> (-60.2555, -5.715)
  line L11 (-61.7986, 5.715) -> (-61.7986, -5.715)
  line L12 (-40.8927, 19.5) -> (-40.8927, 15.6709)
  line L13 (-49.0461, 15.6709) -> (-49.0461, 19.5)
  line L14 (-49.0461, -19.5) -> (-49.0461, -15.6709)
  line L15 (-40.8927, -15.6709) -> (-40.8927, -19.5)
  circle C1 centre (-44.9694, 0) radius 16.3195
  arc A1 centre (-44.9694, -19.5) radius 7.1247 clockwise from (-37.8447, -19.5) to (-52.0941, -19.5)
  arc A2 centre (-44.9694, 0) radius 19.2405 clockwise from (-37.8447, 17.8728) to (-37.8447, -17.8728)
  arc A3 centre (-44.9694, 19.5) radius 7.1247 clockwise from (-52.0941, 19.5) to (-37.8447, 19.5)
  arc A4 centre (-44.9694, 0) radius 19.2405 clockwise from (-52.0941, -17.8728) to (-52.0941, 17.8728)
  arc A5 centre (-44.9694, 19.5) radius 4.2037 clockwise from (-49.1731, 19.5) to (-40.7657, 19.5)
  arc A6 centre (-44.9694, -19.5) radius 4.2037 clockwise from (-40.7657, -19.5) to (-49.1731, -19.5)
  circle C2 centre (-44.9694, 19.5) radius 1.625
  circle C3 centre (-44.9694, -19.5) radius 1.625
  arc A7 centre (-44.9694, 0) radius 16.1925 clockwise from (-40.8927, 15.6709) to (-40.8927, -15.6709)
  arc A8 centre (-44.9694, 19.5) radius 4.0767 clockwise from (-49.0461, 19.5) to (-40.8927, 19.5)
  arc A9 centre (-44.9694, 0) radius 16.1925 clockwise from (-49.0461, -15.6709) to (-49.0461, 15.6709)
  arc A10 centre (-44.9694, -19.5) radius 4.0767 clockwise from (-40.8927, -19.5) to (-49.0461, -19.5)
  circle C4 centre (-36.0794, 0) radius 1.5
  circle C5 centre (-44.9694, 19.5) radius 1.45
  circle C6 centre (-44.9694, -19.5) radius 1.45
  point P23 (-60.2555, 5.715)
  point P24 (-63.3416, 5.715)
  point P25 (-60.2555, -5.715)
  point P26 (-63.3416, -5.715)
  point P27 (-61.7986, 5.715)
  point P28 (-61.7986, -5.715)
  point P29 (-61.7986, -5.715)
  point P30 (-61.7986, 5.715)
  point P31 (-61.7986, 0)
  coincident C1 P23
  coincident A4 P24
  horizontal L9
  coincident C1 P25
  coincident A4 P26
  parallel L9 L10
  midpoint L9 P27
  midpoint L10 P28
  coincident P28 P29
  coincident L9 P30
  perpendicular L9 L11
  coincident P27 P30
  midpoint L11 P31
  concentric C2 C5
  concentric A6 C6
  equal C5 C6
  dimension "d117" distance P29 P30 = 11.43
  dimension "d600" diameter C5 = 2.9
extrude "Extrude8" add sketch "Motor Housing Profile (S)" profile of C1 L1 A1 L2 A2 L3 A3 L4 A4 A5 L5 L6 L7 L8 A6 L9 L10 along normal blind 2.2606
chamfer "Chamfer3" distance 0.5398
extrude "Extrude9" add sketch "Motor Housing Profile (H)" profile of A8 A6 C11 C12 along normal blind 1.27
extrude "Extrude10" cut sketch "Motor Housing Profile (S)" profile of C1 A4 L9 L10 C5 C6 against normal blind 23.7363 and along normal blind 22.86
chamfer "Chamfer4" distance 1.27
fillet "Fillet2" sketch "Profile" radius 1.27
joint "Assemble8" alignAngle -90 alignOffsetX 0 alignOffsetY 0 alignOffsetZ 0
motion_link "MotionLink1" Value1 20 Value2 30
sketch "XY Restriction Holes for Shell" plane through (0, 0, 60.325) normal (0, 0, -1) x axis (1, 0, 0)
  line L1 (0, 0) -> (0, 51.054)
  line L2 (-6.35, 50.6576) -> (-6.35, 41.6831)
  line L3 (6.35, 50.6576) -> (6.35, 41.6831)
  line L4 (-6.35, 46.1703) -> (6.35, 46.1703)
  line L5 (-47.0457, -19.8295) -> (-39.2736, -15.3423)
  line L6 (-40.6957, -30.828) -> (-32.9236, -26.3408)
  line L7 (40.6957, -30.828) -> (32.9236, -26.3408)
  line L8 (47.0457, -19.8295) -> (39.2736, -15.3423)
  circle C1 centre (0, 0) radius 42.164
  circle C2 centre (0, 0) radius 85.725
  circle C3 centre (0, 0) radius 51.054
  circle C4 centre (0, 46.1703) radius 1.5
  circle C5 centre (-39.9847, -23.0852) radius 1.5
  circle C6 centre (39.9847, -23.0852) radius 1.5
  circle C7 centre (0, 46.1703) radius 1.881
  circle C8 centre (39.9847, -23.0852) radius 1.881
  circle C9 centre (-39.9847, -23.0852) radius 1.881
  circle C10 centre (0, 46.1703) radius 1.45
  circle C11 centre (-39.9847, -23.0852) radius 1.45
  circle C12 centre (39.9847, -23.0852) radius 1.45
  point P2 (0, 0)
  point P4 (0, 0)
  point P5 (0, 0)
  point P3 (0, 51.054)
  point P6 (-6.35, 41.6831)
  point P7 (-6.35, 50.6576)
  point P8 (6.35, 41.6831)
  point P9 (6.35, 50.6576)
  point P10 (6.35, 46.1703)
  point P11 (-6.35, 46.1703)
  point P12 (0, 46.1703)
  point P21 (0, 46.1703)
  point P24 (0, 46.1703)
  point P27 (0, 46.1703)
  coincident P2 P4
  coincident P4 P5
  coincident P3 C3
  coincident C1 P6
  coincident C3 P7
  vertical L2
  coincident C1 P8
  coincident C3 P9
  parallel L1 L3
  midpoint L3 P10
  midpoint L2 P11
  midpoint L4 P12
  vertical L1
  horizontal L4
  coincident P12 P21
  coincident P12 P24
  concentric C6 C8
  concentric C5 C9
  equal C8 C9
  equal C7 C8
  coincident P12 P27
  concentric C9 C11
  concentric C8 C12
  equal C11 C12
  equal C10 C11
  dimension "d141" distance C1 C3 = 8.89
  dimension "d142" distance P10 P11 = 12.7
  dimension "d147" diameter C4 = 3
  dimension "d529" distance C4 C7 = 0.381 (= "clearance * 1.5")
  dimension "d530" diameter C10 = 2.9
  dimension "d144" C-Pattern1-Angle = 360
extrude "Extrude3" add sketch "XY Restriction Holes for Shell" profile of C1 C3 L2 L3 L5 L6 L7 L8 C7 C8 C9 C10 C11 C12 along normal blind 3.175
extrude "Extrude7" cut sketch "XY Restriction Holes for Shell" profile of C10 C11 C12 against normal blind 1.0583 (magnitude of "-3.175 mm / 3")
sketch "XY Restriction Plane" plane through (0, 0, 57.15) normal (0, 0, -1) x axis (1, 0, 0)
  line L1 (40.6957, -30.828) -> (32.9236, -26.3408)
  line L2 (39.2736, -15.3423) -> (47.0457, -19.8295)
  line L3 (6.35, 50.6576) -> (6.35, 41.6831)
  line L4 (-6.35, 41.6831) -> (-6.35, 50.6576)
  line L5 (-47.0457, -19.8295) -> (-39.2736, -15.3423)
  line L6 (-32.9236, -26.3408) -> (-40.6957, -30.828)
  arc A1 centre (0, 0) radius 51.054 clockwise from (47.0457, -19.8295) to (40.6957, -30.828)
  arc A2 centre (0, 0) radius 42.164 clockwise from (39.2736, -15.3423) to (32.9236, -26.3408)
  circle C1 centre (0, 0) radius 51.054
  arc A3 centre (0, 0) radius 42.164 clockwise from (-6.35, 41.6831) to (6.35, 41.6831)
  arc A4 centre (0, 0) radius 51.054 clockwise from (-6.35, 50.6576) to (6.35, 50.6576)
  arc A5 centre (0, 0) radius 51.054 clockwise from (-40.6957, -30.828) to (-47.0457, -19.8295)
  arc A6 centre (0, 0) radius 42.164 clockwise from (-32.9236, -26.3408) to (-39.2736, -15.3423)
  circle C2 centre (-39.9847, -23.0852) radius 1.881
  circle C3 centre (39.9847, -23.0852) radius 1.881
  circle C4 centre (0, 46.1703) radius 1.881
  circle C5 centre (39.9847, -23.0852) radius 1.45
  circle C6 centre (0, 46.1703) radius 1.45
  circle C7 centre (-39.9847, -23.0852) radius 1.45
  point P1 (0, 0)
  point P7 (0, 0)
  coincident P1 P7
  tangent A1 C1
extrude "Extrude4" new body sketch "XY Restriction Plane" profile of L1 A1 L2 A2 C1 A3 L3 A4 L4 L5 A5 L6 A6 C2 C3 C4 along normal blind 5.08
sketch "XY Restric. Plane Hole for Driven" plane through (0, 0, 52.07) normal (0, 0, -1) x axis (1, 0, 0)
  circle C1 centre (0, 0) radius 51.054
  circle C2 centre (0, 0) radius 14.4318
  circle C3 centre (0, 0) radius 15.8749
  circle C4 centre (0, 0) radius 16.0443
  circle C5 centre (39.9847, -23.0852) radius 1.881
  circle C6 centre (-39.9847, -23.0852) radius 1.881
  circle C7 centre (0, 46.1703) radius 1.881
  point P4 (1.9903, 15.7497)
  concentric C2 C3
  coincident P4 C3
  dimension "d155" = 0.1693 (= "clearance / 1.5")
extrude "Extrude6" cut sketch "XY Restric. Plane Hole for Driven" profile of C2 C4 against normal blind 35.56
chamfer "Chamfer2" distance 1.27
